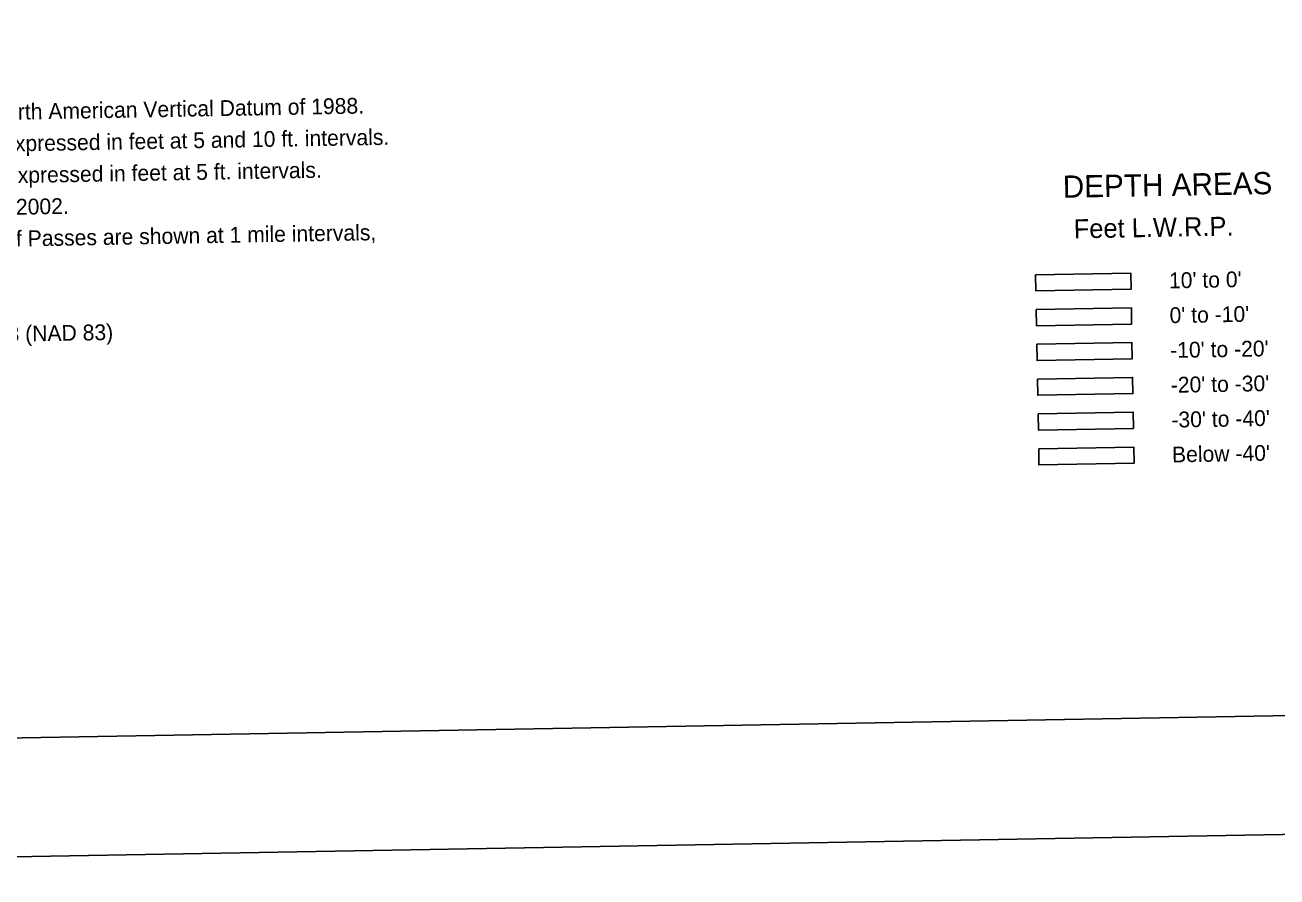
# Model space of a CAD drawing. Extents: x 3903937 to 3942190, y 260677 to 286651.
# Drawn here: x 3910990 to 3917570, y 261260 to 265738 of the extents above; entities that cross this region are included whole.
import ezdxf

# ---------------------------------------------------------------- set-up
doc = ezdxf.new("R2010")
doc.units = 0
for name, color, linetype in [('G-ANNO-NPLT', 7, 'Continuous'), ('V-ANNO-NOTE', 7, 'Continuous'), ('V-ANNO-SYMB', 7, 'Continuous'), ('V-TOPO-DPTH', 7, 'Continuous')]:
    doc.layers.add(name, color=color, linetype=linetype)

msp = doc.modelspace()

# ---------------------------------------------------------------- linework, layer by layer
at = {"layer": 'G-ANNO-NPLT'}
msp.add_lwpolyline([(3904945.8, 261260), (3941606.7, 261905.3), (3941181.4, 286068.2), (3904520.4, 285422.9)], close=True, dxfattribs=at)
at = {"layer": 'V-ANNO-SYMB'}
msp.add_lwpolyline([(3907684.5, 261933.3), (3940762.5, 262515.6), (3940359.2, 285428.6), (3907281.2, 284846.4), (3907684.5, 261933.3)], dxfattribs=at)
at = {"layer": 'V-TOPO-DPTH'}
for points in [[(3916301.2, 264425.4), (3916801.1, 264434.2), (3916802.6, 264349.2), (3916302.7, 264340.4)], [(3916304.4, 264242.4), (3916804.3, 264251.2), (3916805.8, 264166.2), (3916305.9, 264157.4)], [(3916307.6, 264059.5), (3916807.6, 264068.3), (3916809.1, 263983.3), (3916309.1, 263974.5)], [(3916310.9, 263876.5), (3916810.8, 263885.3), (3916812.3, 263800.3), (3916312.4, 263791.5)], [(3916314.1, 263693.5), (3916814, 263702.3), (3916815.5, 263617.3), (3916315.6, 263608.5)], [(3916317.3, 263510.5), (3916817.2, 263519.3), (3916818.7, 263434.4), (3916318.8, 263425.6)]]:
    msp.add_lwpolyline(points, close=True, dxfattribs=at)

# ---------------------------------------------------------------- texts
at = {"layer": 'V-ANNO-NOTE'}
for s, rotation, p in [('All elevations are expressed in feet and refer to North American Vertical Datum of 1988.', 1.00841, (3908460.5, 265196.9)), ('Contours below Low Water Reference Plane are expressed in feet at 5 and 10 ft. intervals.', 1.00841, (3908463.4, 265030.2)), ('Contours above Low Water Reference Plane are expressed in feet at 5 ft. intervals.', 1.00841, (3908466.3, 264863.5)), ('Planimetry from aerial photographs flown January 2002.', 1.00841, (3908469.3, 264696.9)), ('Distances on Mississippi River above Head of Passes are shown at 1 mile intervals,', 1.00841, (3908722.4, 264534.6)), ('Horizontal Datum ..... North American Datum 1983 (NAD 83)', 1.00838, (3908481, 264030.2))]:
    msp.add_text(s, height=83, rotation=rotation, dxfattribs=at).set_placement(p)
at = {"layer": 'V-TOPO-DPTH'}
for s, height, rotation, p in [('DEPTH AREAS', 116.7, 1.00841, (3916444.8, 264829.7)), ('Feet L.W.R.P.', 100, 1.0084, (3916502.3, 264616.5)), ("10' to 0'", 83, 1.0084, (3917002.6, 264353.7)), ("0' to -10'", 83, 1.0084, (3917005.8, 264170.8)), ("-10' to -20'", 83, 1.0084, (3917009, 263987.8)), ("-20' to -30'", 83, 1.0084, (3917012.2, 263804.8)), ("-30' to -40'", 83, 1.0084, (3917015.4, 263621.9)), ("Below -40'", 83, 1.0084, (3917018.7, 263438.9))]:
    msp.add_text(s, height=height, rotation=rotation, dxfattribs=at).set_placement(p)

doc.saveas('drawing.dxf')
